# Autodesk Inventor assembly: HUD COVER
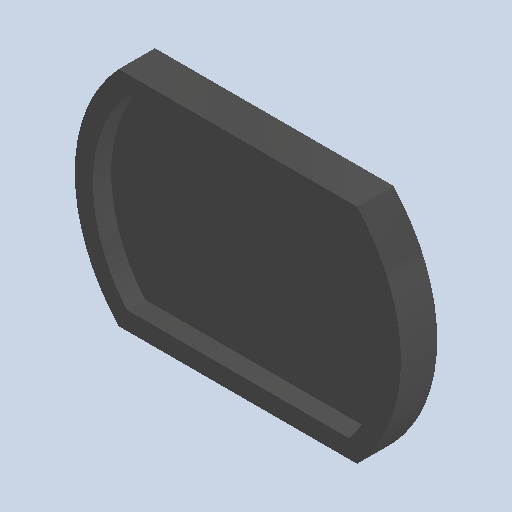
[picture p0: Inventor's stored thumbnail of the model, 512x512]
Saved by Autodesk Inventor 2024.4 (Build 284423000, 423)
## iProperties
Created: 2025-04
Part Number: HUD COVER
Document SubType Name: Assembly
Designer: AdminForWorker
Title: HUD COVER v3
Author: AdminForWorker
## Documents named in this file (2)
- c:\worker\convert-fusion-r02-cosv3\tmp\job-1\12\temp\files\1718eded-1d8f-43a0-9465-10b5a2cd5079\HUD COVER v3.iam
- c:\worker\convert-fusion-r02-cosv3\tmp\job-1\12\temp\files\1718eded-1d8f-43a0-9465-10b5a2cd5079\Component1.iam
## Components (1 placed, 1 different names)
1. Component1:1 [sub-assembly]
